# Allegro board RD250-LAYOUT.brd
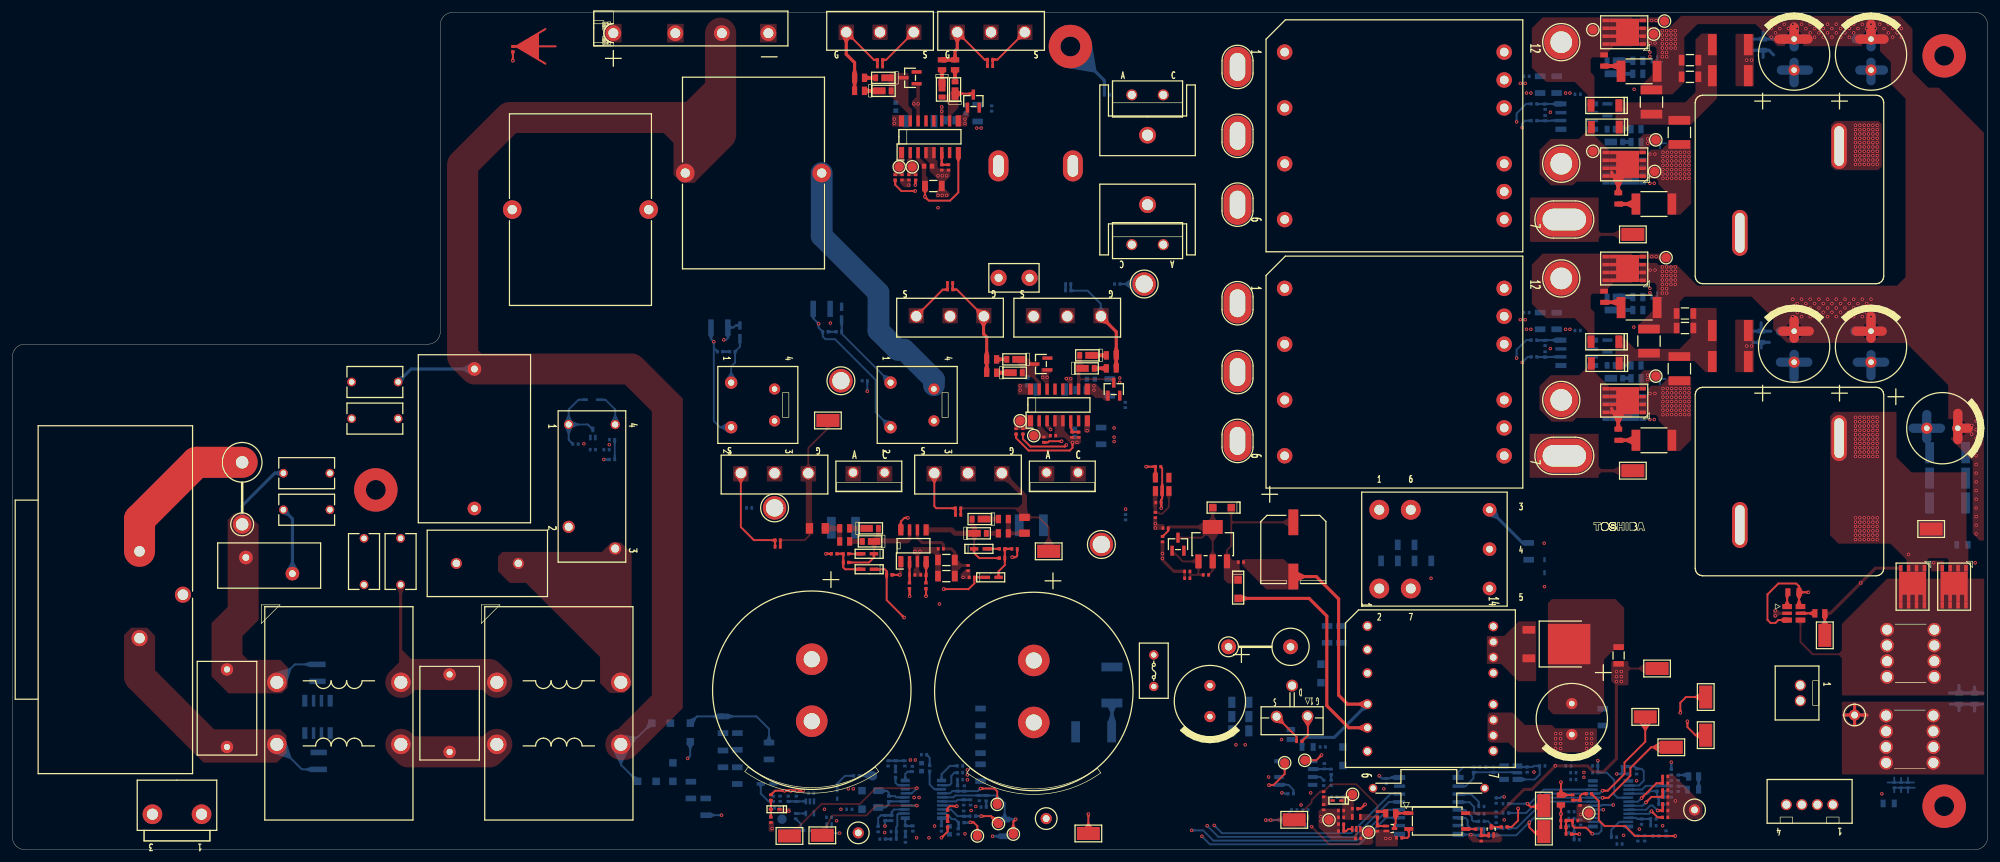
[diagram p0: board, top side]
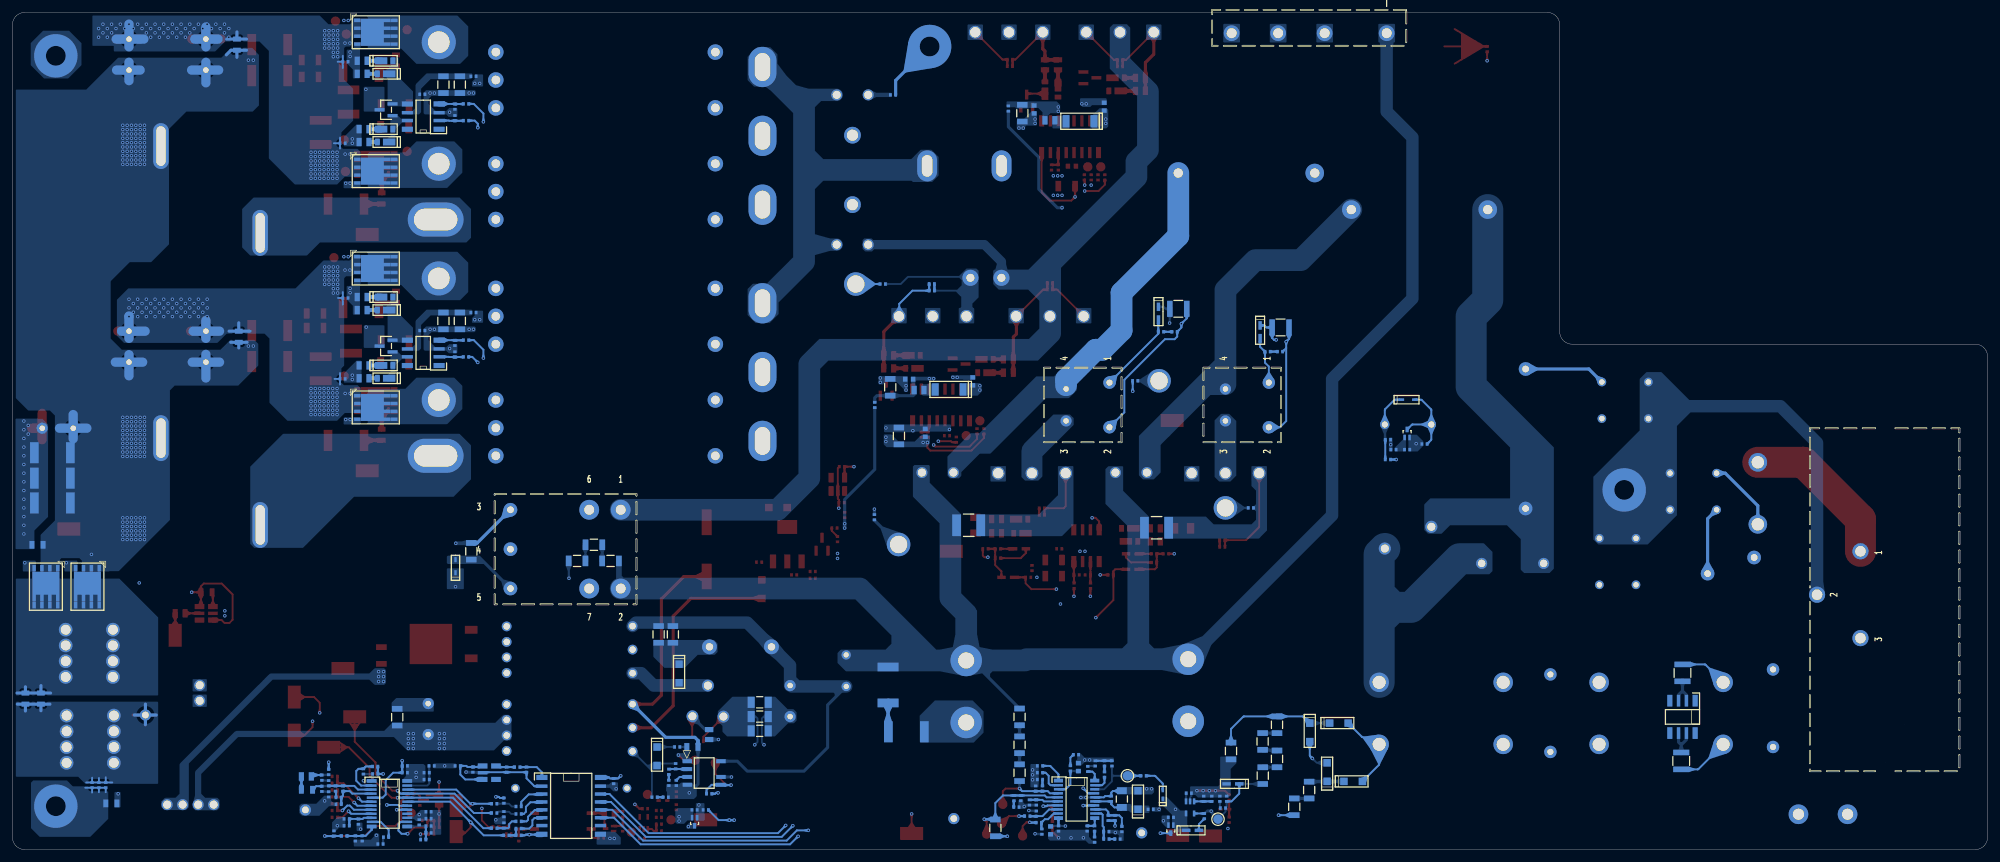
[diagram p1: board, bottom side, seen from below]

Outline 318.5 x 135 mm; copper layers: TOP, CONDUCTIVE2, CONDUCTIVE3, CONDUCTIVE4, CONDUCTIVE5, BOTTOM. Coordinates in mm from the lower left corner of the outline.
Outline path: 0,79.5 0.03,79.85 0.12,80.18 0.27,80.5 0.47,80.79 0.71,81.03 1,81.23 1.32,81.38 1.65,81.47 2,81.5 67,81.5 67.35,81.53 67.68,81.62 68,81.77 68.29,81.97 68.53,82.21 68.73,82.5 68.88,82.82 68.97,83.15 69,83.5 69,133 69.03,133.35 69.12,133.68 69.27,134 69.47,134.29 69.71,134.53 70,134.73 70.32,134.88 70.65,134.97 71,135 316.5,135 316.85,134.97 317.18,134.88 317.5,134.73 317.79,134.53 318.03,134.29 318.23,134 318.38,133.68 318.47,133.35 318.5,133 318.5,2 318.47,1.65 318.38,1.32 318.23,1 318.03,0.71 317.79,0.47 317.5,0.27 317.18,0.12 316.85,0.03 316.5,0 2,0 1.65,0.03 1.32,0.12 1,0.27 0.71,0.47 0.47,0.71 0.27,1 0.12,1.32 0.03,1.65 0,2 0,79.5

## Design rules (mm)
constraint set DEFAULT: 

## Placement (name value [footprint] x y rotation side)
C1  -  [FTP_73]  34.6 22.8 90 top
C2  -  [LOCAL_DE2E3SA222MN3AT02F]  51.2 60.7 180 top
C3  -  [LOCAL_DE2E3SA222MN3AT02F]  51.2 54.8 180 top
C4  -  [LOCAL_DE2E3SA222MN3AT02F]  62.6 50.2 270 top
C5  -  [LOCAL_DE2E3SA222MN3AT02F]  56.7 50.2 270 top
C6  -  [FTP_73]  70.5 22 90 top
C7  -  [LOCAL_DE2E3SA222MN3AT02F]  54.7 69.5 0 top
C8  -  [LOCAL_DE2E3SA222MN3AT02F]  54.7 75.4 0 top
C9  -  [FTP_75]  74.5 66.25 270 top
C11  -  [FTP_65#2]  96.7 62.9 180 bottom
C51  -  [LOCAL_AL_CAP_F30_A]  128.9 25.7 90 top
C52  -  [LOCAL_AL_CAP_F30_A]  164.7 25.5 90 top
C53  -  [FTP_65]  146.9 44.3 0 top
C54  -  [FTP_65]  145.1 44.3 180 top
C55  -  [FTP_15]  150.6 44.1 0 top
C56  -  [FTP_15]  150.6 46.7 0 top
C57  -  [FTP_65]  149.7 48.5 0 top
C58  -  [FTP_65#2]  114.1 80.3 180 bottom
C59  -  [FTP_65]  132.5 47.7 0 top
C60  -  [FTP_65#2]  131.1 83.5 180 bottom
C61  -  [FTP_65]  161.6 48.5 180 top
C62  -  [FTP_65#2]  152.5 2.9 270 bottom
C63  -  [FTP_65#2]  153.4 5.8 90 bottom
C64  -  [FTP_65#2]  155.9 8.3 270 bottom
C65  -  [FTP_65#2]  152.8 13.5 0 bottom
C66  -  [FTP_65#2]  141.2 13.9 90 bottom
C67  -  [FTP_24]  139.6 8.15 90 bottom
C68  -  [FTP_65#2]  141.3 8.2 90 bottom
C69  -  [FTP_67]  151.1 3.1 270 bottom
C70  -  [FTP_65#2]  139.6 3.3 270 bottom
C71  -  [FTP_65#2]  145.2 3.4 270 bottom
C72  -  [FTP_65#2]  144 3.4 270 bottom
C73  -  [FTP_65#2]  142.1 2.9 180 bottom
C74  -  [FTP_65#2]  142.1 1.7 180 bottom
C75  -  [FTP_67]  146.6 13.3 90 bottom
C76  -  [FTP_65#2]  147.9 13.1 90 bottom
C77  -  [FTP_65#2]  153.5 9.85 90 bottom
C78  -  [DC835R1AKP#2]  134 51.9 180 bottom
C79  -  [DC835R1AKP#2]  164.3 52.3 180 bottom
C81  -  [FTP_65]  152.5 55.05 0 top
C82  -  [FTP_65]  123.4 49.9 0 top
C101  -  [FTP_65]  144.55 108.4 90 top
C102  -  [FTP_65]  143.45 108.4 90 top
C103  -  [FTP_65]  150.95 110 90 top
C104  -  [FTP_15]  148.5 107 180 top
C105  -  [KC01670AKP]  147.65 110.2 180 top
C106  -  [FTP_15]  155.65 118.75 90 bottom
C107  -  [KC01670AKP#2]  153.75 119.35 270 bottom
C108  -  [KC01670AKP#2]  142.45 119.8 90 bottom
C109  -  [FTP_65]  139.9 127.35 180 top
C110  -  [FTP_65]  157.65 127.4 180 top
C111  -  [LOCAL_RDER73A104K5B1H03B_A]  164 92.2 180 top
C112  -  [FTP_65]  167.8 66.75 180 top
C113  -  [FTP_65]  161.85 67.45 90 top
C114  -  [FTP_65]  171.95 66.9 90 top
C115  -  [FTP_15]  175.55 66.7 90 bottom
C116  -  [KC01670AKP#2]  171.3 67.2 270 bottom
C117  -  [FTP_15]  176.95 74.55 270 bottom
C118  -  [KC01670AKP#2]  173.9 75.85 0 bottom
C119  -  [KC01670AKP#2]  163.65 75.5 90 bottom
C120  -  [FTP_65]  151.2 90.3 0 top
C121  -  [FTP_65#2]  170.25 90.12 180 bottom
C151  -  [FTP_15]  249 123.35 90 bottom
C152  -  [FTP_15]  246.35 123.35 90 bottom
C153  -  [FTP_65#2]  252.4 121.8 180 bottom
C154  -  [KC00060AKP]  258.95 105 90 top
C155  -  [KC00060AKP]  256.65 127.25 90 top
C156  -  [DC835R1AKP]  264.3 120.55 270 top
C157  -  [DC835R1AKP]  268.8 115.65 90 top
C158  -  [FTP_65#2]  247.15 117.95 90 bottom
C159  -  [FTP_65#2]  247.15 119.8 270 bottom
C201  -  [FTP_15]  246.35 85.25 90 bottom
C202  -  [FTP_15]  249 85.25 90 bottom
C203  -  [FTP_65#2]  252.4 83.7 180 bottom
C204  -  [KC00060AKP]  258.95 66.9 90 top
C205  -  [KC00060AKP]  256.65 89.15 90 top
C206  -  [DC835R1AKP]  263.9 82 270 top
C207  -  [DC835R1AKP]  268.8 77.55 90 top
C208  -  [FTP_65#2]  247.15 79.85 90 bottom
C209  -  [FTP_65#2]  247.15 81.7 270 bottom
C251  -  [FTP_65#2]  255.22 12.4 180 bottom
C252  -  [FTP_65#2]  251.7 12.4 0 bottom
C253  -  [FTP_65#2]  251.7 11.3 0 bottom
C254  -  [FTP_65#2]  260 12.2 180 bottom
C255  -  [FTP_65#2]  251.4 6.1 180 bottom
C256  -  [FTP_65#2]  265.9 8.4 0 bottom
C257  -  [FTP_65#2]  265.2 9.85 90 bottom
C258  -  [KC00060AKP#2]  271 9.65 180 bottom
C301  -  [FTP_15]  122 15.9 90 bottom
C302  -  [FTP_65#2]  122.7 8.2 90 bottom
C303  -  [FTP_65#2]  128.8 9.1 180 bottom
C304  -  [FTP_65#2]  126.4 8.2 90 bottom
C305  -  [FTP_65#2]  125.1 8.2 90 bottom
C306  -  [FTP_65]  217 1.8 0 top
C307  -  [FTP_65]  214.25 4.1 0 top
C308  -  [FTP_65]  214.25 3 0 top
C309  -  [FTP_65#2]  221.55 11.05 270 bottom
C310  -  [FTP_65]  214.25 5.2 0 top
C311  -  [FTP_65#2]  131.7 5.2 0 bottom
C351  -  [FTP_65#2]  235.6 12.9 270 bottom
C401  -  [FTP_13]  193.1 21.45 90 top
C402  -  [FTP_15]  212 34.7 90 bottom
C403  -  [FTP_15]  214.3 34.7 90 bottom
C405  -  [KC00060AKP#2]  208.85 16.55 180 bottom
C407  -  [FTP_65#2]  213.15 8.45 180 bottom
C408  -  [DC845R0AKP]  206.55 48.4 90 top
C409  -  [FTP_65]  198.1 46.35 180 top
C410  -  [FTP_65]  189.45 43.75 0 top
C411  -  [FTP_65]  185.45 50.05 90 top
C412  -  [FTP_65]  184.8 55.95 180 top
C413  -  [FTP_65]  184.75 61.75 180 top
C414  -  [SIK00180ATP_RD244_A]  224.65 9.9 0 top
C451  -  [FTP_13]  251.45 18.55 90 top
C452  -  [FTP_65#2]  244.25 12.9 270 bottom
C453  -  [FTP_65#2]  238.8 12.9 270 bottom
C501  -  [FTP_13]  287.3 130.7 270 top
C502  -  [FTP_13]  299.7 130.7 270 top
C503  -  [FTP_13]  313.7 67.95 180 top
C504  -  [FTP_13]  287.3 83.6 270 top
C505  -  [FTP_13]  299.7 83.6 270 top
C506  -  [KC00060AKP#2]  282 82.7 90 bottom
C507  -  [KC00060AKP#2]  282.3 129.8 90 bottom
C508  -  [KC00060AKP#2]  314.45 49.15 0 bottom
C509  -  [KC00060AKP]  287.2 41.5 0 top
C510  -  [KC00060AKP#2]  313.9 24.35 270 bottom
C511  -  [KC00060AKP#2]  316.4 24.35 270 bottom
C512  -  [KC00060AKP#2]  302.55 7.45 0 bottom
C513  -  [FTP_65#2]  303.45 10.4 90 bottom
CN1  -  [FTP_9]  4.7 40.3 270 top
CN2  -  [DJA415_ALG]  30.5 5.7 180 top
CN101  -  [LOCAL_LONGHOLE_250_450]  197.55 104 270 top
CN102  -  [LOCAL_LONGHOLE_250_450]  197.55 115.1 90 top
CN103  -  [LOCAL_LONGHOLE_250_450]  197.55 126.2 90 top
CN104  -  [LOCAL_LONGHOLE_250_450]  197.55 65.9 90 top
CN105  -  [LOCAL_LONGHOLE_250_450]  197.55 77 90 top
CN106  -  [LOCAL_LONGHOLE_250_450]  197.55 88.1 90 top
CN151  -  [LOCAL_TH350_P550]  249.75 110.6 0 top
CN152  -  [LOCAL_TH350_P550]  249.75 130.2 0 top
CN153  -  [LOCAL_LONGHOLE_350_700]  250.25 101.6 0 top
CN201  -  [LOCAL_TH350_P550]  249.75 72.5 0 top
CN202  -  [LOCAL_TH350_P550]  249.75 92.1 0 top
CN203  -  [LOCAL_LONGHOLE_350_700]  250.25 63.5 0 top
CN501  -  [LOCAL_7460305_A]  306.1 31.65 270 top
CN502  -  [LOCAL_7460305_A]  305.95 17.8 270 top
CN503  -  [CUK02330ATP]  288.3 26.5 270 top
CN504  -  [CUP10050ATP]  293.55 7.25 180 top
D1  -  [FTP_28]  93.45 72.55 0 bottom
D51  -  [MMK01670AKP]  109.3 18.9 90 bottom
D52  -  [MMK01670AKP]  104.6 20.4 0 bottom
D53  -  [MMK01670AKP]  106.5 12.5 270 bottom
D54  -  [MMK01670AKP]  102.3 11 0 bottom
D55  -  [LOCAL_GSIB2580_A]  96.9 131.65 0 top
D56  -  [LOCAL_TO_220_2L_A]  135.56 60.8 0 top
D57  -  [LOCAL_TO_220_2L_A]  166.76 60.8 0 top
D58  -  [FTP_20]  117.31 83.5 90 bottom
D59  -  [US2H_A]  138.4 51.8 0 top
D60  -  [US2H_A]  138.3 49.7 180 top
D61  -  [FTP_20]  137.9 47.7 0 top
D62  -  [FTP_20]  137.9 45.2 0 top
D63  -  [FTP_20]  133.7 86.5 90 bottom
D64  -  [US2H_A]  156 53.3 180 top
D65  -  [US2H_A]  155.8 51 0 top
D66  -  [FTP_20]  156.1 48.5 180 top
D67  -  [FTP_20]  158 43.9 180 top
D68  -  [FTP_85]  137 8 270 bottom
D101  -  [FTP_81]  146.35 117.45 180 bottom
D102  -  [US2H_A]  140.45 122.35 0 top
D103  -  [US2H_A]  140.45 124.45 180 top
D104  -  [FTP_27]  144.75 124.45 90 top
D105  -  [US2H_A]  149.9 122.6 270 top
D106  -  [US2H_A]  152 122.55 90 top
D107  -  [FTP_27]  154.95 120.7 0 top
D108  -  [DD504V]  185.58 97.55 180 top
D109  -  [DD504V]  180.5 121.7 0 top
D110  -  [FTP_81]  167.45 74.2 180 bottom
D111  -  [US2H_A]  161.6 76.9 0 top
D112  -  [US2H_A]  161.6 79.05 180 top
D113  -  [FTP_27]  165.85 78.3 90 top
D114  -  [US2H_A]  173.35 79.7 180 top
D115  -  [US2H_A]  173.2 77.6 0 top
D116  -  [FTP_27]  177.6 74.25 0 top
D151  -  [US2H_A]  258.4 116.17 180 bottom
D152  -  [US2H_A]  258.4 114.1 0 bottom
D153  -  [FTP_27]  258.25 119.3 90 bottom
D154  -  [US2H_A]  258.4 127.2 180 bottom
D156  -  [US2H_A]  258.4 125.1 0 bottom
D157  -  [FTP_81]  256.85 116.5 0 top
D158  -  [FTP_81]  256.8 120 0 top
D201  -  [US2H_A]  258.4 78.08 180 bottom
D202  -  [US2H_A]  258.4 76 0 bottom
D203  -  [FTP_27]  258.25 81.2 90 bottom
D204  -  [US2H_A]  258.4 89.1 180 bottom
D206  -  [US2H_A]  258.4 87 0 bottom
D207  -  [FTP_81]  256.85 78.4 0 top
D208  -  [FTP_81]  256.8 81.9 0 top
D251  -  [FTP_28]  247.05 45.7 270 bottom
D302  -  [D8K022]  121.7 10.6 180 bottom
D303  -  [FTP_20]  128.2 3.1 0 bottom
D304  -  [D8101D1AKP]  133 8.9 270 bottom
D305  -  [D8101D1AKP]  123 6.5 0 top
D306  -  [D8101D1AKP]  213.6 7.9 0 top
D401  -  [MMK01670AKP]  211 28.4 90 bottom
D402  -  [MMK01670AKP]  214.55 15.05 90 bottom
D403  -  [MMK01670AKP]  197.65 42 90 top
D404  -  [MMK01670AKP]  195.05 55.15 0 top
D405  -  [FTP_27]  187.95 49.25 0 top
D451  -  [DIC8V2]  249.6 33.15 270 top
DP1  -  [FTP_71]  166.7 5 0 top
DP51  -  [FTP_57]  173.5 2.6 0 top
DP52  -  [DTP815]  155.6 2.2 0 top
DP53  -  [FTP_57]  131.5 69.2 0 top
DP54  -  [DTP815]  159 4.2 0 top
DP55  -  [FTP_57]  167.1 48.1 0 top
DP56  -  [DTP815]  161.4 2.5 180 top
DP57  -  [FTP_57]  125.3 2.2 0 top
DP58  -  [FTP_57]  130.6 2.3 0 top
DP59  -  [FTP_71]  136.4 2.7 0 top
DP60  -  [DTP815]  158.8 7.3 0 top
DP61  -  [DTP815]  138.7 11.9 180 bottom
DP101  -  [DTP815]  143 110.1 0 top
DP102  -  [DTP815]  145.1 110.1 0 top
DP103  -  [DTP815]  162.5 69.15 0 top
DP104  -  [DTP815]  164.7 66.75 90 top
DP151  -  [DTP815]  254.85 112.6 0 top
DP152  -  [DTP815]  265 114.45 0 top
DP153  -  [DTP815]  264.8 109.35 0 top
DP154  -  [DTP815]  254.85 132.2 0 top
DP155  -  [DTP815]  266.4 133.6 0 top
DP156  -  [DTP815]  264.65 131.5 0 top
DP157  -  [FTP_57]  261.3 99.2 0 top
DP201  -  [DTP815]  265 76.35 0 top
DP202  -  [DTP815]  266.65 95.45 0 top
DP203  -  [FTP_57]  261.3 61.1 0 top
DP251  -  [FTP_57]  246.95 7.1 90 top
DP252  -  [FTP_57]  263.3 21.4 180 top
DP253  -  [FTP_57]  267.5 16.5 180 top
DP254  -  [FTP_57]  246.95 2.9 270 top
DP255  -  [FTP_57]  273.05 18.45 90 top
DP256  -  [FTP_57]  273.05 24.6 270 top
DP257  -  [FTP_71]  271.25 6.4 0 top
DP258  -  [DTP815]  254.2 5.9 0 top
DP301  -  [DTP815]  124.1 4.9 0 bottom
DP302  -  [DTP815]  216.1 8.9 0 top
DP303  -  [DTP815]  218.7 2.8 0 top
DP304  -  [DTP815]  212.3 4.8 0 top
DP401  -  [DTP815]  208.4 14.4 0 top
DP402  -  [DTP815]  205.15 14 90 top
DP403  -  [FTP_57]  206.7 4.8 180 top
DP404  -  [FTP_116]  122.9 55.1 0 top
DP405  -  [FTP_116]  175.6 49.2 0 top
DP406  -  [FTP_116]  133.6 75.6 0 top
DP407  -  [FTP_116]  182.5 91.2 0 top
DP451  -  [FTP_57]  265.2 29.2 0 top
DP501  -  [FTP_71]  297.05 21.7 0 top
DP502  -  [FTP_57]  292.25 34.55 90 top
DP503  -  [FTP_57]  309.4 51.7 0 top
F1  -  [LITTELFUSE_0215_PHI5_5_V_A_2]  37.05 62.45 270 top
F401  -  [F_I_808__0440_LF]  184.05 28.85 270 top
HS1  -  [LOCAL_BPUS15_25_A]  183.04 104 0 top
HS2  -  [LOCAL_BPUS15_25_A]  183.04 115.2 180 top
IC1  -  [FTP_60]  49.2 21.4 180 bottom
IC51  -  [FTP_112]  145.3 49 0 top
IC52  -  [FTP_128]  146.9 8.1 270 bottom
IC101  -  [I8K123]  147.95 114.95 0 top
IC102  -  [I8K123]  168.75 71.7 0 top
IC151  -  [FTP_112]  252.25 118.2 90 bottom
IC201  -  [FTP_112]  252.25 80.1 90 bottom
IC251  -  [FTP_61]  257.7 7.4 90 bottom
IC301  -  [MM00730AKP#2]  128.6 6.8 180 bottom
IC302  -  [MM00730AKP]  216.7 4.3 0 top
IC303  -  [LOCAL_4PIN_SO6L_A]  229.75 4.6 270 top
IC304  -  [LOCAL_I8K0A8]  228.4 7.05 90 bottom
IC401  -  [LOCAL_SOIC_7_A]  206.95 12.35 180 bottom
IC402  -  [MM01320AKP]  193.55 49.25 0 top
IC403  -  [DI8G1K]  185.4 58.9 0 top
IC451  -  [DI8G1K#2]  241.6 12.4 90 bottom
IC501  -  [SOT_23_6_KA]  287.25 38.1 270 top
L1  -  [LOCAL_LDFW013412YV_V0E_A]  52.64 21.97 0 top
L2  -  [LOCAL_LDFW013412YV_V0E_A]  88.11 21.97 0 top
L51  -  [FTP_118]  91.6 103.2 270 top
L52  -  [FTP_118]  119.5 109.1 270 top
L53  -  [FTP_55]  129.8 51.8 180 top
L54  -  [FTP_55]  163.2 52.3 90 top
L101  -  [LOCAL_TMSD_Y3001]  165 110.25 270 top
L151  -  [LOCAL_CTW18A27UH]  286.55 106.45 90 top
L201  -  [LOCAL_CTW18A27UH]  286.55 59.35 90 top
NOREF  -  []  168.8 71.7 0 top
NOREF#2  -  []  148 114.95 0 top
NOREF#3  -  [unnamed#2]  181.5 7 0 top
NOREF#4  -  []  170.6 129.5 0 top
NOREF#5  -  []  311.5 128 0 top
NOREF#6  -  []  58.6 58 0 top
NOREF#7  -  []  87.5 129.5 0 top
NOREF#8  -  [unnamed#2]  7 76.5 0 top
NOREF#9  -  []  311.5 7 0 top
NOREF#10  -  [unnamed#2]  73.5 128 0 top
NOREF#11  -  [unnamed#2]  180 128 0 top
NOREF#12  -  []  7 7 0 top
NOREF#13  -  []  253.8 50.3 0 top
Q1  -  [MM00340AKP]  93.6 67.1 180 bottom
Q51  -  [RDP10020ATP]  128.34 60.7 180 top
Q52  -  [RDP10020ATP]  159.54 60.7 180 top
Q101  -  [RDP10020ATP]  134.46 131.8 0 top
Q102  -  [RDP10020ATP]  152.36 131.8 0 top
Q103  -  [RDP10020ATP]  156.64 86 180 top
Q104  -  [RDP10020ATP]  175.54 86 180 top
Q151  -  [LOCAL_SOPADVANCE_E_01_A]  259.9 110.5 90 top
Q152  -  [LOCAL_SOPADVANCE_E_01_A]  259.9 109.4 270 bottom
Q153  -  [LOCAL_SOPADVANCE_E_01_A]  259.9 131.8 90 top
Q154  -  [LOCAL_SOPADVANCE_E_01_A]  259.9 131.8 270 bottom
Q201  -  [LOCAL_SOPADVANCE_E_01_A]  259.9 72.4 90 top
Q202  -  [LOCAL_SOPADVANCE_E_01_A]  259.9 71.3 270 bottom
Q203  -  [LOCAL_SOPADVANCE_E_01_A]  259.9 93.7 90 top
Q204  -  [LOCAL_SOPADVANCE_E_01_A]  259.9 93.7 270 bottom
Q301  -  [MM00340AKP]  222.2 3.4 270 top
Q302  -  [MM00340AKP]  131.7 3.3 0 bottom
Q303  -  [MM00340AKP]  208.5 4.5 0 bottom
Q351  -  [MM00340AKP]  238.45 3 0 top
Q401  -  [LOCAL_TO_220SIS_02_A]  206.35 21.45 180 top
Q501  -  [LOCAL_SOPADVANCE_E_01_A]  306.4 42.4 180 top
Q502  -  [LOCAL_SOPADVANCE_E_01_A]  313.1 42.4 180 top
Q503  -  [LOCAL_SOPADVANCE_E_01_A]  313.1 42.4 0 bottom
Q504  -  [LOCAL_SOPADVANCE_E_01_A]  306.4 42.4 0 bottom
R1  -  [FTP_49]  49.2 28.5 270 bottom
R2  -  [FTP_49]  49.4 14.3 270 bottom
R3  -  [LOCAL_Y5JA_330JPTL3_5_A]  76.58 46.15 180 top
R4  -  [KC00050AKP#2]  96.7 66.1 0 bottom
R5  -  [KC00050AKP#2]  93.6 64.5 180 bottom
R6  -  [KC00050AKP#2]  90.8 65.4 0 bottom
R7  -  [KC00050AKP#2]  95.8 64.5 0 bottom
R51  -  [KC00050AKP]  154.1 45.4 90 top
R52  -  [FTP_49]  114.01 84.2 180 bottom
R53  -  [KC00050AKP#2]  116.1 80.3 180 bottom
R54  -  [DR810K]  134.2 49.7 180 top
R55  -  [DR810K]  134.2 51.8 180 top
R56  -  [KC00050AKP]  123.4 48.8 0 top
R57  -  [KC00050AKP]  134.4 46.3 180 top
R58  -  [KC00050AKP]  134.4 47.7 180 top
R59  -  [KC00050AKP]  141.4 44.3 0 top
R60  -  [FTP_49]  130.5 87.2 180 bottom
R61  -  [KC00050AKP#2]  133.3 83.5 180 bottom
R62  -  [DR810K]  159.8 51 0 top
R63  -  [DR810K]  159.8 53.3 0 top
R64  -  [KC00050AKP]  152.5 53.95 0 top
R65  -  [KC00050AKP]  159.6 47 0 top
R66  -  [KC00050AKP]  159.6 48.5 0 top
R67  -  [KC00050AKP]  154.7 43.9 180 top
R68  -  [KC00050AKP#2]  153 4.35 0 bottom
R69  -  [KC00050AKP#2]  154.85 5.4 0 bottom
R70  -  [FTP_50#2]  109.4 9.6 270 bottom
R71  -  [FTP_50#2]  111.8 6.9 270 bottom
R72  -  [FTP_50#2]  160 3.5 90 bottom
R73  -  [KC00050AKP#2]  157 8.3 270 bottom
R74  -  [KC00050AKP#2]  156.6 6.85 180 bottom
R76  -  [KC00050AKP#2]  152.8 12.4 0 bottom
R77  -  [KC00050AKP#2]  145.1 13 90 bottom
R78  -  [KC00050AKP#2]  143.9 13.9 90 bottom
R79  -  [KC00050AKP#2]  153.4 7.6 270 bottom
R80  -  [KC00050AKP#2]  154.5 7.6 270 bottom
R81  -  [KC00050AKP]  150.8 5.9 90 top
R82  -  [KC00050AKP]  150.8 4.1 90 top
R83  -  [KC00050AKP#2]  142.4 12.1 90 bottom
R84  -  [KC00050AKP#2]  142.4 13.9 90 bottom
R85  -  [KC00050AKP#2]  134.95 6.5 180 bottom
R86  -  [KC00050AKP#2]  140.7 5.1 270 bottom
R87  -  [KC00050AKP#2]  141.8 5.1 270 bottom
R88  -  [KC00050AKP#2]  149.8 3.4 270 bottom
R89  -  [KC00050AKP#2]  144 1.6 270 bottom
R90  -  [KC00050AKP#2]  140.3 1.7 180 bottom
R91  -  [KC00050AKP#2]  147 15.3 180 bottom
R92  -  [FTP_50#2]  156.1 21.4 270 bottom
R93  -  [FTP_50#2]  156.1 16.9 270 bottom
R94  -  [FTP_50#2]  156.1 12.4 270 bottom
R95  -  [KC00050AKP#2]  152.4 9.85 90 bottom
R96  -  [KC00050AKP#2]  152.8 11.3 0 bottom
R97  -  [KC00050AKP]  144.65 42.55 90 top
R98  -  [KC00050AKP]  147.3 42.55 90 top
R101  -  [R8100A#2]  177.3 26.55 270 bottom
R102  -  [R8100A#2]  174.35 19 180 bottom
R103  -  [KC00050AKP]  145.65 108.4 270 top
R104  -  [KC00050AKP]  142.35 108.4 270 top
R105  -  [KC00050AKP]  149.85 110 270 top
R106  -  [KC00050AKP#2]  157.9 119.5 270 bottom
R107  -  [DR810K#2]  151.2 117.6 180 bottom
R108  -  [DR810K]  136.6 122.35 180 top
R109  -  [DR810K]  136.6 124.45 180 top
R110  -  [KC00050AKP]  139.9 126.25 180 top
R111  -  [DR810K]  149.9 126.55 90 top
R112  -  [DR810K]  152 126.55 90 top
R113  -  [KC00050AKP]  157.65 126.3 180 top
R114  -  [KC00050AKP]  166.3 66.1 270 top
R115  -  [KC00050AKP]  162.95 67.45 270 top
R116  -  [KC00050AKP]  170.85 66.9 270 top
R117  -  [KC00050AKP#2]  179.45 71.7 270 bottom
R118  -  [DR810K#2]  172.3 74.1 180 bottom
R119  -  [DR810K]  157.9 76.9 180 top
R120  -  [DR810K]  157.9 79.05 180 top
R121  -  [KC00050AKP]  151.2 91.4 0 top
R122  -  [DR810K]  177.2 79.7 0 top
R123  -  [DR810K]  177.2 77.6 0 top
R124  -  [KC00050AKP#2]  170.25 91.22 180 bottom
R151  -  [KC00050AKP#2]  244.15 124.7 180 bottom
R152  -  [DR810K#2]  261.8 116.17 180 bottom
R153  -  [DR810K#2]  261.8 114.1 180 bottom
R154  -  [KC00050AKP#2]  265.25 113.9 0 bottom
R155  -  [FTP_106]  264.7 104.1 180 top
R156  -  [DR810K#2]  262.1 127.2 180 bottom
R157  -  [DR810K#2]  262.1 125.1 180 bottom
R158  -  [KC00050AKP#2]  264.8 127.05 0 bottom
R159  -  [FTP_106]  262.3 125.5 180 top
R160  -  [FTP_50]  270.5 127.31 0 top
R161  -  [FTP_50]  270.5 124.61 0 top
R162  -  [R8100A]  277 129.8 0 top
R163  -  [R8100A]  277 124.8 0 top
R164  -  [KC00050AKP#2]  245.35 117.55 180 bottom
R165  -  [KC00050AKP#2]  245.35 120.25 180 bottom
R201  -  [KC00050AKP#2]  244.15 86.6 180 bottom
R202  -  [DR810K#2]  261.8 78.08 180 bottom
R203  -  [DR810K#2]  261.8 76 180 bottom
R204  -  [KC00050AKP#2]  265.25 75.9 0 bottom
R205  -  [FTP_106]  264.7 66 180 top
R206  -  [DR810K#2]  262.1 89.1 180 bottom
R207  -  [DR810K#2]  262.1 87 180 bottom
R208  -  [KC00050AKP#2]  264.8 88.95 0 bottom
R209  -  [FTP_106]  262.3 87.4 180 top
R210  -  [FTP_50]  269.7 86.45 0 top
R211  -  [FTP_50]  269.7 84.11 0 top
R212  -  [R8100A]  277 83.7 0 top
R213  -  [R8100A]  277 78.7 0 top
R214  -  [KC00050AKP#2]  245.35 79.45 180 bottom
R215  -  [KC00050AKP#2]  245.35 82.15 180 bottom
R251  -  [FTP_50#2]  244.5 48.1 90 bottom
R252  -  [KC00050AKP#2]  255.22 13.5 180 bottom
R253  -  [KC00050AKP]  266.52 11.8 180 top
R254  -  [KC00050AKP]  266.52 10.7 180 top
R255  -  [KC00050AKP]  266.52 9.6 180 top
R256  -  [KC00050AKP]  266.52 8.5 180 top
R257  -  [KC00050AKP]  266.52 7.4 180 top
R258  -  [KC00050AKP]  266.52 6.3 180 top
R259  -  [KC00050AKP]  266.52 5.2 180 top
R260  -  [KC00050AKP#2]  250.9 13.5 180 bottom
R261  -  [KC00050AKP#2]  258.25 2 0 bottom
R262  -  [KC00050AKP#2]  259.15 0.9 0 bottom
R263  -  [KC00050AKP#2]  264.6 3.85 180 bottom
R264  -  [KC00050AKP#2]  262.7 4.5 270 bottom
R265  -  [KC00050AKP#2]  264.6 4.95 180 bottom
R266  -  [KC00050AKP#2]  252.9 4.4 270 bottom
R267  -  [KC00050AKP#2]  251.4 3.8 180 bottom
R268  -  [KC00050AKP#2]  252.25 1.6 180 bottom
R269  -  [KC00050AKP#2]  251.4 2.7 180 bottom
R270  -  [KC00050AKP]  250.95 2.5 0 top
R271  -  [KC00050AKP]  250.1 4.7 0 top
R272  -  [KC00050AKP#2]  261.9 12.6 90 bottom
R273  -  [KC00050AKP#2]  260 13.4 180 bottom
R274  -  [KC00050AKP]  252 4.7 0 top
R275  -  [KC00050AKP]  250.1 3.6 0 top
R276  -  [KC00050AKP#2]  251.4 5 180 bottom
R277  -  [KC00050AKP]  252.8 7.55 90 top
R278  -  [KC00050AKP]  254.2 9 180 top
R279  -  [KC00050AKP#2]  266.65 2.6 270 bottom
R280  -  [KC00050AKP#2]  265 2.2 180 bottom
R281  -  [KC00050AKP#2]  262.1 1.8 270 bottom
R282  -  [KC00050AKP]  251.6 8.4 90 top
R283  -  [KC00050AKP#2]  263.2 1.8 270 bottom
R284  -  [DR810K]  249.7 8 90 top
R285  -  [KC00050AKP#2]  265.9 7.3 0 bottom
R286  -  [KC00050AKP#2]  266.4 9.85 270 bottom
R287  -  [KC00050AKP#2]  267.5 12.5 270 bottom
R288  -  [KC00050AKP#2]  268.6 11.6 270 bottom
R289  -  [KC00050AKP#2]  267.5 10.7 270 bottom
R290  -  [KC00050AKP#2]  268.6 9.8 270 bottom
R291  -  [KC00050AKP#2]  267.5 8.9 270 bottom
R292  -  [DR810K#2]  271.1 11.8 0 bottom
R301  -  [FTP_50#2]  114.58 20.13 90 bottom
R302  -  [FTP_50#2]  116.9 17.44 90 bottom
R303  -  [FTP_50#2]  114.58 14.63 90 bottom
R304  -  [FTP_50#2]  116.88 11.93 90 bottom
R305  -  [KC00050AKP#2]  123.3 6.7 0 bottom
R306  -  [KC00050AKP#2]  123.8 8.2 90 bottom
R307  -  [KC00050AKP#2]  126.3 5.4 90 bottom
R308  -  [KC00050AKP#2]  136.1 11.9 0 bottom
R309  -  [FTP_50#2]  222.05 46.55 180 bottom
R310  -  [FTP_50#2]  224.74 49.15 180 bottom
R311  -  [FTP_50#2]  227.45 46.55 180 bottom
R312  -  [KC00050AKP]  214.25 6.3 0 top
R313  -  [KC00050AKP]  216.5 6.6 0 top
R314  -  [KC00050AKP]  220.1 5.7 90 top
R315  -  [KC00050AKP]  220.1 3.4 90 top
R316  -  [DR810K]  222.25 5.85 180 top
R317  -  [KC00050AKP]  223.6 1.9 0 top
R318  -  [KC00050AKP#2]  206.7 6.4 0 bottom
R319  -  [KC00050AKP#2]  208.5 6.4 0 bottom
R320  -  [KC00050AKP]  122.3 4.8 270 top
R321  -  [KC00050AKP]  122.3 8.4 270 top
R322  -  [KC00050AKP]  211.44 8.92 90 top
R323  -  [KC00050AKP]  211.44 6.82 90 top
R351  -  [KC00050AKP]  236.45 3.3 180 top
R352  -  [KC00050AKP]  236.85 1.8 90 top
R353  -  [KC00050AKP]  240.55 3.65 0 top
R354  -  [KC00050AKP#2]  236.88 6.95 0 bottom
R355  -  [KC00050AKP#2]  240.8 7.4 180 bottom
R356  -  [KC00050AKP#2]  239.25 7.9 90 bottom
R357  -  [KC00050AKP#2]  236.88 5.75 0 bottom
R358  -  [KC00050AKP#2]  240.8 5.9 180 bottom
R359  -  [KC00050AKP#2]  239.25 5.7 270 bottom
R360  -  [KC00050AKP#2]  236.88 4.55 0 bottom
R361  -  [KC00050AKP#2]  240.8 3.45 180 bottom
R362  -  [KC00050AKP#2]  239.25 3.9 90 bottom
R363  -  [KC00050AKP#2]  236.88 3.4 0 bottom
R364  -  [KC00050AKP#2]  238.85 2.3 180 bottom
R365  -  [KC00050AKP#2]  236.88 2.3 180 bottom
R401  -  [FTP_98]  206.1 32.7 180 top
R402  -  [DR810K#2]  206.15 18.55 270 bottom
R403  -  [KC00050AKP]  207.5 17.45 0 top
R404  -  [KC00140AKP01]  198 23.75 180 bottom
R405  -  [KC00140AKP01]  198 21.45 180 bottom
R406  -  [KC00140AKP01]  198 19.15 180 bottom
R407  -  [KC00050AKP#2]  206.15 9 0 bottom
R408  -  [KC00050AKP#2]  211.3 16.55 180 bottom
R409  -  [KC00050AKP#2]  211.55 13.45 270 bottom
R410  -  [KC00050AKP#2]  212.65 12.55 270 bottom
R411  -  [KC00050AKP#2]  212.65 10.75 270 bottom
R412  -  [KC00050AKP#2]  211.45 10.75 270 bottom
R413  -  [KC00050AKP#2]  214.95 8.45 180 bottom
R414  -  [KC00050AKP]  189.45 44.85 0 top
R415  -  [KC00050AKP]  192.45 44.3 0 top
R416  -  [KC00050AKP]  185.95 51.85 0 top
R417  -  [KC00050AKP]  184.3 53.95 90 top
R418  -  [KC00050AKP#2]  118.8 55.1 180 bottom
R419  -  [KC00050AKP#2]  179.5 53.6 90 bottom
R420  -  [KC00050AKP#2]  137.45 75.6 0 bottom
R421  -  [KC00050AKP#2]  178.15 91.2 180 bottom
R422  -  [KC00050AKP]  80.7 129.1 90 top
R423  -  [KC00050AKP#2]  176.5 121.7 0 bottom
R451  -  [FTP_50#2]  256.45 21.35 270 bottom
R452  -  [FTP_50]  259 31.3 270 top
R453  -  [KC00050AKP#2]  246.7 13.5 0 bottom
R454  -  [KC00050AKP#2]  237.1 13.3 0 bottom
R501  -  [R8100A#2]  312.05 64 0 bottom
R502  -  [R8100A#2]  312.05 59.9 0 bottom
R503  -  [R8100A#2]  312.05 55.9 0 bottom
R504  -  [DR810K]  291.45 38.1 0 top
R505  -  [KC00050AKP#2]  304.55 10.39 270 bottom
R506  -  [KC00050AKP#2]  305.65 10.4 270 bottom
RV1  -  [FTP_120]  41.4 45.8 0 top
RY1  -  [LOCAL_G5PZ_1A]  89.7 68.55 270 top
T51  -  [FTP_94]  120.2 71.7 270 top
T52  -  [FTP_94]  145.9 71.7 270 top
T101  -  [FTP_96]  229.3 48.45 0 top
T151  -  [LOCAL_TAM0545]  222.85 115.1 270 top
T201  -  [LOCAL_TAM0545]  222.85 77 270 top
T401  -  [LOCAL_TAM_PQ20_36_5]  228.65 25.95 270 top

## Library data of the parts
C1 C6 = PRT_17: alternate symbols: (T:FTP_73;B:FTP_74)
C2 C3 = DE2B3SA101KA3BT02F
C4 C5 C7 C8 = DE2E3SA222MN3AT02F: alternate symbols: (T:Local_DE2E3SA222MN3AT02F;B:Local_DE2E3SA222MN3AT02F_B)
C9 = PRT_18: alternate symbols: (T:FTP_75;B:FTP_76)
C11 C53 C54 C57-C66 C68 C70-C74 C76 C77 C81 C82 C101-C103 C109 C110 C112-C114 C120 C121 C153 C158 C159 C203 C208 C209 C251-C257 C302-C311 C351 C407 C409-C413 C452 C453 C513 = PRT_52: alternate symbols: (T:FTP_65;B:FTP_66)
C51 C52 = EKHE421VSN561MR35Z: alternate symbols: (T:Local_AL_CAP_f30_A;B:Local_AL_CAP_f30_A_B)
C55 C56 C104 C106 C115 C117 C151 C152 C201 C202 C301 C402 C403 = PRT_46: alternate symbols: (T:FTP_15;B:FTP_16)
C67 = PRT_51: alternate symbols: (T:FTP_24;B:FTP_25)
C69 C75 = PRT_48: alternate symbols: (T:FTP_67;B:FTP_68)
C78 C79 = C4532: alternate symbols: (T:DC835R1AKP;B:DC835R1BKP)
C105 C107 C108 C116 C118 C119 = C1608: alternate symbols: (T:KC01670AKP;B:KC01670BKP)
C111 = RDER73A104K5B1H03B: alternate symbols: (T:Local_RDER73A104K5B1H03B_A;B:Local_RDER73A104K5B1H03B_A_B)
C154 C155 C204 C205 C405 C506-C512 = GRM21BC71E106KE01: alternate symbols: (T:KC00060AKP;B:KC00060BKP)
C156 C157 C206 C207 = K0301583: alternate symbols: (T:DC835R1AKP;B:DC835R1BKP)
C258 = C2012: alternate symbols: (T:KC00060AKP;B:KC00060BKP)
C401 C451 C501-C505 = PRT_3: alternate symbols: (T:FTP_13;B:FTP_14)
C408 = EMLA350ARA331MJA0G: alternate symbols: (T:DC845R0AKP;B:DC845R0BKP)
C414 = DE2B3SA221KA3BT02F: alternate symbols: (T:SIK00180ATP_RD244_A;B:SIK00180ATP_RD244_A_B)
CN1 = PRT_61: alternate symbols: (T:FTP_9;B:FTP_10)
CN2 = G36220401068: alternate symbols: (T:DJA415_ALG;B:DA415R_ALG)
CN101-CN106 = Longhole_2R5-4R5: alternate symbols: (T:Local_LONGHOLE_250_450;B:Local_LONGHOLE_250_450_B)
CN151 CN152 CN201 CN202 = TH_phi_3R5: alternate symbols: (T:Local_TH350_P550;B:Local_TH350_P550_B)
CN153 CN203 = Longhole_3R5-7R0: alternate symbols: (T:Local_LONGHOLE_350_700;B:Local_LONGHOLE_350_700_B)
CN501 CN502 = 7460305: alternate symbols: (T:Local_7460305_A;B:Local_7460305_A_B)
CN503 = K2203993: alternate symbols: (T:CUK02330ATP;B:CUK02330BTP)
CN504 = K22S0019: alternate symbols: (T:CUP10050ATP;B:CUP10050BTP)
D1 D251 = PRT_26: alternate symbols: (T:FTP_28;B:FTP_32)
D51-D54 = CRG04A: alternate symbols: (T:MMK01670AKP;B:MMK01670BKP)
D55 = GSIB2580: alternate symbols: (T:Local_GSIB2580_A;B:NO_D0001A)
D56 D57 = SBD_TO-220-2L: alternate symbols: (T:Local_TO_220_2L_A;B:Local_TO_220_2L_A_B)
D58 D61-D63 D66 D67 D303 = PRT_27: alternate symbols: (T:FTP_20;B:FTP_22)
D59 D60 D64 D65 D102 D103 D105 D106 D111 D112 D114 D115 D151 D152 D154 D156 D201 D202 D204 D206 = CUHS15S30: alternate symbols: (T:US2H_A;B:US2H_B)
D68 = PRT_6: alternate symbols: (T:FTP_85;B:FTP_86)
D101 D110 D157 D158 D207 D208 = PRT_14: alternate symbols: (T:FTP_81;B:FTP_82)
D104 D107 D113 D116 D153 D203 D405 = PRT_25: alternate symbols: (T:FTP_27;B:FTP_31)
D108 D109 = TRS8E65H: alternate symbols: (T:DD504V;B:DD504V_B)
D302 = ZenerDiode_USC-01: alternate symbols: (T:D8K022;B:D9K022)
D304-D306 = 1SS405: alternate symbols: (T:D8101D1AKP;B:D8101D1BKP)
D401 = CRF03A: alternate symbols: (T:MMK01670AKP;B:MMK01670BKP)
D402 D403 = GDM420000387: alternate symbols: (T:MMK01670AKP;B:MMK01670BKP)
D404 = K4200730: alternate symbols: (T:MMK01670AKP;B:MMK01670BKP)
D451 = NJM78M05SDL1-TE1: alternate symbols: (T:DIC8V2;B:DIC9V2)
DP1 DP59 = PRT_49: alternate symbols: (T:FTP_71;B:FTP_72)
DP51 DP53 DP55 DP57 DP58 DP157 DP203 DP251-DP256 DP403 DP451 DP502 DP503 = PRT_44: alternate symbols: (T:FTP_57;B:FTP_58)
DP52 DP54 DP56 DP60 DP61 DP101-DP104 DP151-DP156 DP201 DP202 DP258 DP301-DP304 DP401 DP402 = DTP815: alternate symbols: (T:DTP815;B:DTP915)
DP257 DP501 = PRT_34: alternate symbols: (T:FTP_71;B:FTP_72)
DP404-DP407 = PRT_39: alternate symbols: (T:FTP_116;B:FTP_117)
F1 = 0215015.MXEP: alternate symbols: (T:Littelfuse_0215_phi5_5_V_A_2;B:Littelfuse_0215_phi5_5_V_B_2)
F401 = 808****0440_LF: alternate symbols: (T:F_I_808__0440_LF;B:F_I_808__0440_LF_B)
HS1 HS2 = BPUS15-25: alternate symbols: (T:Local_BPUS15_25_A;B:Local_BPUS15_25_B)
IC1 = PRT_45: alternate symbols: (T:FTP_60;B:FTP_63)
IC51 IC151 IC201 = PRT_63: alternate symbols: (T:FTP_112;B:FTP_113)
IC52 = PRT_59: alternate symbols: (T:FTP_128;B:FTP_129)
IC101 IC102 = UCC21330: alternate symbols: (T:I8K123;B:I9K123)
IC251 = PRT_16: alternate symbols: (T:FTP_61;B:FTP_64)
IC301 IC302 = GDM470001845: alternate symbols: (T:MM00730AKP;B:MM00730BKP)
IC303 = TLP385: alternate symbols: (T:Local_4pin_SO6L_A;B:Local_4pin_SO6L_B)
IC304 = DCL540C01: alternate symbols: (T:Local_I8K0A8;B:LocalI9K0A8)
IC401 = UCC28711DR: alternate symbols: (T:Local_SOIC_7_A;B:Local_SOIC_7_B)
IC402 = LM317MDCY: alternate symbols: (T:MM01320AKP;B:MM01320BKP)
IC403 IC451 = TCR1HF50B: alternate symbols: (T:DI8G1K;B:DI9G1K)
IC501 = LM74700-Q1: alternate symbols: (T:SOT_23_6_KA;B:SOT_23_6_KB)
L1 L2 = LDFW013412YV-V0E: alternate symbols: (T:Local_LDFW013412YV_V0E_A;B:Local_LDFW013412YV_V0E_B)
L51 L52 = PRT_41: alternate symbols: (T:FTP_118;B:FTP_119)
L53 L54 = PRT_30: alternate symbols: (T:FTP_55;B:FTP_56)
L101 = TMSD-Y3001: alternate symbols: (T:Local_TMSD_Y3001;B:Local_TMSD_Y3001_B)
L151 L201 = CTW18A27uH: alternate symbols: (T:Local_CTW18A27uH;B:Local_CTW18A27uH_B)
Q1 Q301-Q303 Q351 = GDM410000663: alternate symbols: (T:MM00340AKP;B:MM00340BKP)
Q51 Q52 = TK125N60Z1: alternate symbols: (T:RDP10020ATP;B:RDP10020BTP)
Q101-Q104 = TK095N65Z5: alternate symbols: (T:RDP10020ATP;B:RDP10020BTP)
Q151-Q154 Q201-Q204 Q501-Q504 = NchMOSFET_SOPAdvance(E)-01: alternate symbols: (T:Local_SOPAdvance_E_01_A;B:Local_SOPAdvance_E_01_B)
Q401 = K4100860: alternate symbols: (T:Local_TO_220SIS_02_A;B:NO_Q00001)
R1 R2 R52 R60 = PRT_23: alternate symbols: (T:FTP_49;B:FTP_52)
R3 = Y5JA-330JPTL3_5: alternate symbols: (T:Local_Y5JA_330JPTL3_5_A;B:Local_Y5JA_330JPTL3_5_A_B)
R4-R7 R51 R53 R56-R59 R61 R64-R69 R73 R74 R76-R91 R95-R98 R103-R106 R110 R113-R117 R121 R124 R151 R154 R158 R164 R165 R201 R204 R208 R214 R215 R252-R283 R285-R291 R305-R308 R312-R315 R317-R323 R351-R365 R403 R407-R423 R453 R454 R505 R506 = GDM010004481: alternate symbols: (T:KC00050AKP;B:KC00050BKP)
R54 R55 R62 R63 R107-R109 R111 R112 R118-R120 R122 R123 R152 R153 R156 R157 R202 R203 R206 R207 R284 R292 R316 R402 R504 = R2012: alternate symbols: (T:DR810K;B:DR910K)
R70-R72 R92-R94 R160 R161 R210 R211 R251 R301-R304 R309-R311 R451 R452 = PRT_5: alternate symbols: (T:FTP_50;B:FTP_51)
R101 R102 R501-R503 = GDM010001640: alternate symbols: (T:R8100A;B:R9100A)
R155 R159 R205 R209 = PRT_43: alternate symbols: (T:FTP_106;B:FTP_107)
R162 R163 R212 R213 = CRGH2512J620R: alternate symbols: (T:R8100A;B:R9100A)
R401 = PRT_54: alternate symbols: (T:FTP_98;B:FTP_99)
R404-R406 = R3216: alternate symbols: (T:KC00140AKP01;B:KC00140BKP01)
RV1 = PRT_37: alternate symbols: (T:FTP_120;B:FTP_121)
RY1 = G5PZ-1A: alternate symbols: (T:Local_G5PZ_1A;B:Local_G5PZ_1A_B)
T51 T52 = PRT_7: alternate symbols: (T:FTP_94,T52_FTP_94;B:FTP_95)
T101 = PRT_65: alternate symbols: (T:FTP_96;B:FTP_97)
T151 T201 = TAM0545: alternate symbols: (T:Local_TAM0545;B:Local_TAM0545_B)
T401 = WT2020B: alternate symbols: (T:Local_TAM_PQ20_36_5;B:Local_TAM_PQ20_36_5_B)

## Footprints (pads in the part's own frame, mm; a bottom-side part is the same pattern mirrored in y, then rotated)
CUK02330ATP
  round 1.778 hole 1.3: 1(0,0) 2(2.5,0)
CUP10050ATP
  round 1.778 hole 1.3: 1(0,0) 2(2.5,0) 3(5,0) 4(7.5,0)
D8K022
  rect 1.36x0.55 smd: A(-1.025,0) C(1.025,0)
D8101D1AKP
  rect 0.7x0.4 smd: A(-0.7,0) C(0.7,0)
DC835R1AKP
  rect 1.41x3.5 smd: 1(-1.95,0) 2(1.95,0)
DC835R1AKP#2
  rect 1.41x3.5 smd: 1(1.95,0) 2(-1.95,0)
DC845R0AKP
  rect 4.15x1.6 smd: 1(-4.375,0) 2(4.375,0)
DD504V
  round 1.778 hole 1.3: A(0,0) C(5.08,0)
DI8G1K
  rect 0.825x1.56 smd: 1(-1.087,-1.075) 3(1.087,-1.075) 4(1.087,1.075) 5(-1.087,1.075)
  rect 0.55x1.56 smd: 2(0,-1.075)
DI8G1K#2
  rect 0.825x1.56 smd: 1(1.087,1.075) 3(-1.087,1.075) 4(-1.087,-1.075) 5(1.087,-1.075)
  rect 0.55x1.56 smd: 2(0,1.075)
DIC8V2
  rect 1.25x2.049 smd: 1(-2.3,-5.075) 3(2.3,-5.075)
  rect 6.5x6.85 smd: 2(0,1.425)
DJA415_ALG
  round 3.175 hole 1.8: 1(0,0) 3(7.92,0)
  round 0 hole 1.8: 2(3.96,0)
DR810K
  rect 0.83x1.35 smd: 1(-0.8,0) 2(0.8,0)
DR810K#2
  rect 0.83x1.35 smd: 1(0.8,0) 2(-0.8,0)
DTP815
  round 1.5 smd: 1(0,0)
F_I_808__0440_LF
  round 1.5 hole 0.85: 1(-2.54,0) 2(2.54,0)
FTP_9
  round 0.01 hole 2.6x4 unplated: (-26.2,11.8) (26.2,11.8)
  round 0.01 hole 3.6 unplated: (-20.05,8.75) (20.05,8.75)
  round 2.6 hole 1.7: 1(-7.8,15.8) 2(-0.8,22.8) 3(6.2,15.8)
FTP_13
  round 1.8 hole 0.9: 1(0,0) 2(5,0)
FTP_15
  rect 0.92x1.7 smd: 1(-1.35,0) 2(1.35,0)
FTP_20
  rect 1.36x0.55 smd: A(-1.025,0) C(1.025,0)
FTP_24
  rect 1.1x1.6 smd: 1(1.35,0) 2(-1.35,0)
FTP_27
  rect 0.55x1.61 smd: A(-0.95,-1.05) C(0,1.05) NC(0.95,-1.05)
FTP_28
  rect 0.824x0.4 smd: A(-1.05,0) C(1.05,0)
FTP_49
  rect 0.895x2.6 smd: 1(1.363,0) 2(-1.363,0)
FTP_50
  rect 0.92x1.7 smd: 1(-1.35,0) 2(1.35,0)
FTP_50#2
  rect 0.92x1.7 smd: 1(1.35,0) 2(-1.35,0)
FTP_55
  rect 1.17x1.7 smd: 1(-1.275,0) 2(1.275,0)
FTP_57
  rect 3.7x2.1 smd: 1(0,0)
FTP_60
  rect 0.825x1.885 smd: 1(2.042,2.612) 4(-2.042,2.612) 5(-2.042,-2.612) 8(2.042,-2.612)
  rect 0.55x1.885 smd: 2(0.635,2.612) 3(-0.635,2.612) 6(-0.635,-2.612) 7(0.635,-2.612)
FTP_61
  rect 0.6x1.585 smd: 1(3.675,2.862) 12(-3.675,2.862) 13(-3.675,-2.862) 24(3.675,-2.862)
  rect 0.4x1.585 smd: 2(2.925,2.862) 3(2.275,2.862) 4(1.625,2.862) 5(0.975,2.862) 6(0.325,2.862) 7(-0.325,2.862) 8(-0.975,2.862) 9(-1.625,2.862) 10(-2.275,2.862) 11(-2.925,2.862) 14(-2.925,-2.862) 15(-2.275,-2.862) 16(-1.625,-2.862) 17(-0.975,-2.862) 18(-0.325,-2.862) 19(0.325,-2.862) 20(0.975,-2.862) 21(1.625,-2.862) 22(2.275,-2.862) 23(2.925,-2.862)
FTP_65
  rect 0.45x0.55 smd: 1(-0.425,0) 2(0.425,0)
FTP_65#2
  rect 0.45x0.55 smd: 1(0.425,0) 2(-0.425,0)
FTP_67
  rect 0.72x0.8 smd: 1(0.64,0) 2(-0.64,0)
FTP_71
  round 1.8 hole 1.1: 1(0,0)
FTP_73
  round 2 hole 1: 1(-6.25,0) 2(6.25,0)
FTP_75
  round 2.2 hole 1.1: 1(-11.25,0) 2(11.25,0)
FTP_81
  rect 1.1x2 smd: A(-2.25,0) C(2.25,0)
FTP_85
  rect 1.212x1.2 smd: A(-1.494,0) C(1.494,0)
FTP_94
  round 2 hole 1: 1(-3.6,-4.3) 2(3.6,-4.3)
  round 1.8 hole 0.9: 3(2.575,2.7) 4(-2.575,2.7)
FTP_96
  round 3.2 hole 1.6: 1(-8.89,6.35) 2(-8.89,-6.35) 6(-3.81,6.35) 7(-3.81,-6.35)
  round 2.2 hole 1.1: 3(8.89,6.35) 4(8.89,0) 5(8.89,-6.35)
FTP_98
  round 2.4 hole 1.2: 1(0,0) 2(10,0)
FTP_106
  rect 1.405x3.4 smd: 1(-2.902,0) 2(2.902,0)
FTP_112
  rect 0.825x1.795 smd: 1(-2.042,-2.558) 4(2.042,-2.558) 5(2.042,2.558) 8(-2.042,2.558)
  rect 0.55x1.795 smd: 2(-0.635,-2.558) 3(0.635,-2.558) 6(0.635,2.558) 7(-0.635,2.558)
FTP_116
  round 3.8 hole 2.8: 1(0,0)
FTP_118
  round 3 hole 1.5: 1(0,-11) 2(0,11)
FTP_120
  round 2.2 hole 1.1: 1(-3.75,1.3) 2(3.75,-1.3)
FTP_128
  rect 0.6x1.46 smd: 1(-3.025,-2.925) 10(3.025,-2.925) 11(3.025,2.925) 20(-3.025,2.925)
  rect 0.4x1.46 smd: 2(-2.275,-2.925) 3(-1.625,-2.925) 4(-0.975,-2.925) 5(-0.325,-2.925) 6(0.325,-2.925) 7(0.975,-2.925) 8(1.625,-2.925) 9(2.275,-2.925) 12(2.275,2.925) 13(1.625,2.925) 14(0.975,2.925) 15(0.325,2.925) 16(-0.325,2.925) 17(-0.975,2.925) 18(-1.625,2.925) 19(-2.275,2.925)
I8K123
  rect 0.825x1.795 smd: 1(-4.583,-2.558) 8(4.583,-2.558) 9(4.583,2.558) 16(-4.583,2.558)
  rect 0.55x1.795 smd: 2(-3.175,-2.558) 3(-1.905,-2.558) 4(-0.635,-2.558) 5(0.635,-2.558) 6(1.905,-2.558) 7(3.175,-2.558) 10(3.175,2.558) 11(1.905,2.558) 12(0.635,2.558) 13(-0.635,2.558) 14(-1.905,2.558) 15(-3.175,2.558)
KC00050AKP
  rect 0.45x0.55 smd: 1(-0.425,0) 2(0.425,0)
KC00050AKP#2
  rect 0.45x0.55 smd: 1(0.425,0) 2(-0.425,0)
KC00060AKP
  rect 0.8x1.25 smd: 1(-0.9,0) 2(0.9,0)
KC00060AKP#2
  rect 0.8x1.25 smd: 1(0.9,0) 2(-0.9,0)
KC00140AKP01
  rect 1.15x1.8 smd: 1(1.375,0) 2(-1.375,0)
KC01670AKP
  rect 0.72x0.8 smd: 1(-0.64,0) 2(0.64,0)
KC01670AKP#2
  rect 0.72x0.8 smd: 1(0.64,0) 2(-0.64,0)
LITTELFUSE_0215_PHI5_5_V_A_2
  round 3 hole 2: 1(0,0) 2(10,0)
LOCAL_4PIN_SO6L_A
  rect 0.6x1.45 smd: 1(-1.27,-4.575) 3(1.27,-4.575) 4(1.27,4.575) 6(-1.27,4.575)
LOCAL_7460305_A
  round 2.2 hole 1.6: 1(-3.81,-3.81) 2(-1.27,-3.81) 3(1.27,-3.81) 4(3.81,-3.81) 5(3.81,3.81) 6(1.27,3.81) 7(-1.27,3.81) 8(-3.81,3.81)
LOCAL_AL_CAP_F30_A
  round 0.01 hole 0.8 unplated: (0,0)
  round 5.08 hole 2.6: 1(-5,0) 2(5,0)
LOCAL_BPUS15_25_A
  round 2.7 hole 1.8: 1(0,0)
LOCAL_CTW18A27UH
  oval 7.4x2.5 hole 6.4x1.5: F(7,-8) S(-7,8)
LOCAL_DE2E3SA222MN3AT02F
  round 1.4 hole 0.9: 1(0,0) 2(7.5,0)
LOCAL_G5PZ_1A
  round 1.5 hole 1: 1(0,0) 4(0,7.5)
  round 1.95 hole 1.3: 2(16.5,0) 3(20,7.5)
LOCAL_GSIB2580_A
  round 2.54 hole 1.6: 1(0,0) 2(10,0) 3(17.5,0) 4(25,0)
LOCAL_I8K0A8
  rect 0.825x1.795 smd: 1(4.582,4.72) 8(-4.582,4.72) 9(-4.582,-4.72) 16(4.582,-4.72)
  rect 0.55x1.795 smd: 2(3.175,4.72) 3(1.905,4.72) 4(0.635,4.72) 5(-0.635,4.72) 6(-1.905,4.72) 7(-3.175,4.72) 10(-3.175,-4.72) 11(-1.905,-4.72) 12(-0.635,-4.72) 13(0.635,-4.72) 14(1.905,-4.72) 15(3.175,-4.72)
LOCAL_LDFW013412YV_V0E_A
  round 3.15 hole 2.1: 1(-10,5) 2(10,5) 3(10,-5) 4(-10,-5)
LOCAL_LONGHOLE_250_450
  oval 6.5x4.5 hole 4.5x2.5: 1(0,0)
LOCAL_LONGHOLE_350_700
  oval 9x5.5 hole 7x3.5: 1(0,0)
LOCAL_RDER73A104K5B1H03B_A
  round 2.6 hole 1.3: 1(-0.02,0) 2(4.98,0)
LOCAL_SOIC_7_A
  rect 1.528x0.65 smd: 1(-2.711,1.905) 2(-2.711,0.635) 3(-2.711,-0.635) 4(-2.711,-1.905) 5(2.711,-1.905) 6(2.711,-0.635) 7(2.711,1.905)
LOCAL_SOPADVANCE_E_01_A
  custom 1.09x1.09 smd: (0,0)
  rect 0.55x1.05 smd: 1(-1.905,-2.975) 2(-0.635,-2.975) 3(0.635,-2.975) 4(1.905,-2.975) 5(1.905,2.975) 6(0.635,2.975) 7(-0.635,2.975) 8(-1.905,2.975)
LOCAL_TAM0545
  round 2.5 hole 1.4: 1(-13.5,-17.7) 3(-4.5,-17.7) 4(4.5,-17.7) 6(13.5,-17.7) 7(13.5,17.7) 8(9,17.7) 9(4.5,17.7) 10(-4.5,17.7) 11(-9,17.7) 12(-13.5,17.7)
LOCAL_TAM_PQ20_36_5
  round 1.575 hole 1.067: 1(-10.1,-10.15) 2(-6.3,-10.15) 3(-2.5,-10.15) 4(2.5,-10.15) 5(6.3,-10.15) 6(10.1,-10.15) 7(10.04,10.15) 8(7.54,10.15) 9(5.04,10.15) 10(2.54,10.15) 11(-2.54,10.15) 12(-5.04,10.15) 13(-7.54,10.15) 14(-10.04,10.15)
LOCAL_TH350_P550
  round 5.5 hole 3.5: 1(0,0)
LOCAL_TMSD_Y3001
  oval 5x3.2 hole 3.5x1.7: 1(0,-6) 2(0,6)
LOCAL_TO_220_2L_A
  round 1.778 hole 1.3: A(0,0) C(5.08,0)
LOCAL_TO_220SIS_02_A
  round 1.9 hole 1.3: D(0,-5) G(-2.5,-0.05) S(2.5,0)
LOCAL_Y5JA_330JPTL3_5_A
  round 1.778 hole 1.2: 1(-5,0) 2(5,0)
MM00340AKP
  rect 0.5x0.9 smd: D(0,0.65)
  rect 0.4x0.9 smd: G(-0.4,-0.65) S(0.4,-0.65)
MM00730AKP
  rect 0.4x0.95 smd: 1(-0.65,-0.975) 2(0,-0.975) 3(0.65,-0.975) 4(0.65,0.975) 5(-0.65,0.975)
MM00730AKP#2
  rect 0.4x0.95 smd: 1(0.65,0.975) 2(0,0.975) 3(-0.65,0.975) 4(-0.65,-0.975) 5(0.65,-0.975)
MM01320AKP
  rect 1x2.25 smd: 1(-2.3,-2.775) 2(0,-2.775) 3(2.3,-2.775)
  rect 3.2x2.25 smd: 4(0,2.775)
MMK01670AKP
  rect 1.212x1.2 smd: A(-1.494,0) C(1.494,0)
R8100A
  rect 1.405x3.4 smd: 1(-2.902,0) 2(2.902,0)
R8100A#2
  rect 1.405x3.4 smd: 1(2.902,0) 2(-2.902,0)
RDP10020ATP
  round 1.9 hole 1.65: D(5.44,0) G(0,0) S(10.88,0)
SIK00180ATP_RD244_A
  round 1.4 hole 0.9: 1(-5.25,0) 2(12.75,0)
SOT_23_6_KA
  rect 0.825x1.56 smd: 1(-1.087,-1.075) 3(1.087,-1.075) 4(1.087,1.075) 6(-1.087,1.075)
  rect 0.55x1.56 smd: 2(0,-1.075) 5(0,1.075)
unnamed#2
  round 0.01 hole 3.2 unplated: (0,0)
US2H_A
  custom 0.2x0.2 smd: A(1.25,0)
  rect 2x1.1 smd: C(-0.65,0)

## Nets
P48V: C510.2 C511.2 C512.2 CN501.1 CN501.2 CN501.3 CN501.4 CN501.5 CN501.6 CN501.7 CN501.8 CN503.1 IC501.4 Q501.5 Q501.6 Q501.7 Q501.8 Q502.5 Q502.6 Q502.7 Q502.8 Q503.5 Q503.6 Q503.7 Q503.8 Q504.5 Q504.6 Q504.7 Q504.8
VCC5R0_1: C104.2 C105.2 C115.2 C116.2 C309.2 C413.2 IC101.3 IC101.8 IC102.3 IC102.8 IC304.16 IC403.5
VCC5R0_2: C351.2 IC304.1 R454.2
VCC12R0_1: C11.2 D1.C DP403.1 IC51.1 IC51.8 R4.1 R51.1 R59.2 R67.2 R85.1 R106.1 R117.1 R314.2 R316.2 R318.2 R320.2 R322.2 R416.1 R417.1 RY1.4
VCC12R0_2: CN504.1 CN504.2 DP451.1 IC303.6 R151.1 R201.1 R260.1 R452.2 R453.1
ACIN: C301.2 D51.C D52.C R301.1
CONN002: C119.1 C120.1 CN101.1 CN104.1 D113.A IC102.14 Q103.S Q104.D R121.1
CONN003: CN103.1 CN106.1 D108.A D109.C L101.2
CONN004: C501.2 C502.2 C503.2 C504.2 C505.2 C506.2 C507.2 C508.2 C509.2 DP503.1 IC501.3 IC501.6 L151.F L201.F Q501.1 Q501.2 Q501.3 Q502.1 Q502.2 Q502.3 Q503.1 Q503.2 Q503.3 Q504.1 Q504.2 Q504.3 R162.2 R163.2 R212.2 R213.2 R287.2 R501.2 R502.2 R503.2
CS: D251.C R282.2 R284.2
CSA: D58.C D62.C DP52.1 R52.2 R59.1 R68.1
CSB: D63.C D67.C DP54.1 R60.2 R67.1 R69.1
FG1: C2.1 C3.1 C4.1 C5.1 C7.1 C8.1 CN1.2
FG2: C512.1 C513.2 R505.1 R506.1
HS1_1: R422.2
HS1_2: R423.2
LGND: C151.1 C152.1 C153.1 C156.1 C157.1 C158.1 C159.1 C201.1 C202.1 C203.1 C206.1 C207.1 C208.1 C209.1 C251.1 C252.1 C253.1 C254.1 C255.1 C351.1 C414.2 C451.1 C452.1 C453.1 C501.1 C502.1 C503.1 C504.1 C505.1 C506.1 C507.1 C508.1 C510.1 C511.1 C513.1 CN502.1 CN502.2 CN502.3 CN502.4 CN502.5 CN502.6 CN502.7 CN502.8 CN503.2 CN504.3 CN504.4 D153.C D203.C DP153.1 DP156.1 DP257.1 DP501.1 IC151.3 IC201.3 IC251.24 IC304.2 IC304.8 IC451.2 IC501.2 Q151.1 Q151.2 Q151.3 Q152.1 Q152.2 Q152.3 Q153.1 Q153.2 Q153.3 Q154.1 Q154.2 Q154.3 Q201.1 Q201.2 Q201.3 Q202.1 Q202.2 Q202.3 Q203.1 Q203.2 Q203.3 Q204.1 Q204.2 Q204.3 Q351.S R154.1 R155.1 R158.1 R159.1 R160.1 R161.1 R204.1 R205.1 R208.1 R209.1 R210.1 R211.1 R251.1 R252.1 R253.1 R254.1 R255.1 R256.1 R257.1 R258.1 R259.1 R262.1 R264.1 R267.1 R269.1 R271.1 R273.1 R275.1 R276.1 R281.1 R283.1 R284.1 R285.1 R291.1 R352.1 R356.1 R359.1 R362.1 R365.1 R451.1 R501.1 R502.1 R503.1 R505.2 R506.2 T101.3 T401.8 T401.9
OUTA1: IC304.14 R104.2
OUTA2: DP251.1 IC251.22 R355.2
OUTB1: IC304.13 R103.2
OUTB2: DP252.1 IC251.21 R358.2
OUTC1: IC304.12 R115.2
OUTC2: DP253.1 IC251.20 R361.2
OUTD1: IC304.11 R114.2
OUTD2: DP254.1 IC251.19 R364.2
OUTE: DP255.1 IC251.18 R164.1 R214.1
OUTF: DP256.1 IC251.17 R165.1 R215.1
PFC_OFF: C66.2 DP61.1 IC52.18 R308.1
PFC_OUT: C51.2 C52.2 C78.2 C79.2 D55.1 D56.C D57.C DP51.1 F401.1 R92.2 R101.2 R309.1 T101.2
PN: C11.1 C51.1 C52.1 C53.1 C54.1 C55.1 C56.1 C57.1 C58.1 C59.1 C60.1 C61.1 C62.1 C63.1 C64.1 C65.1 C66.1 C67.1 C68.1 C69.1 C70.1 C71.1 C73.1 C75.1 C77.1 C78.1 C79.1 C81.1 C82.1 C101.1 C102.1 C103.1 C104.1 C105.1 C106.1 C107.1 C110.1 C111.1 C112.1 C113.1 C114.1 C115.1 C116.1 C117.1 C118.1 C121.1 C301.1 C302.1 C303.1 C304.1 C305.1 C306.1 C307.1 C308.1 C309.1 C310.1 C311.1 C401.1 C405.1 C407.1 C408.1 C409.1 C410.1 C411.1 C412.1 C413.1 C414.1 D55.4 D68.A D107.A D109.A D116.A D302.A DP1.1 DP59.1 DP304.1 HS1.1 HS2.1 IC51.3 IC52.16 IC101.4 IC101.5 IC101.9 IC102.4 IC102.5 IC102.9 IC301.2 IC302.2 IC304.9 IC304.15 IC401.4 IC403.2 Q1.S Q51.S Q52.S Q102.S Q104.S Q301.S Q302.S Q303.S R5.1 R6.1 R52.1 R56.1 R60.1 R64.1 R74.1 R76.1 R78.1 R79.1 R80.1 R82.1 R84.1 R88.1 R89.1 R90.1 R91.1 R96.1 R102.1 R105.2 R113.1 R116.2 R124.1 R306.1 R312.1 R315.1 R317.1 R319.1 R321.1 R323.1 R404.1 R405.1 R406.1 R411.1 R412.1 R414.1 R418.1 R419.1 R420.1 R421.1 R422.1 R423.1 T51.2 T52.2 T401.4
RY_OFF: C311.2 D303.C D304.C IC301.4 Q302.G R4.2 R7.1
SIG1: C1.2 C2.2 F1.2 L1.1 R1.2 RV1.1
SIG2: C1.1 C3.2 CN1.3 CN2.3 L1.4 R2.1 RV1.2
SIG6: C8.2 C9.1 D52.A D54.A D55.3 L2.3 L52.1
SIG8: C9.2 D51.A D53.A D55.2 L51.1 R3.2 RY1.2
SIG9: IC1.2 IC1.3 R1.1
SIG10: IC1.6 IC1.7 R2.2
SIG11: D57.A L52.2 T52.4
SIG0012: C7.2 L2.2 R3.1 RY1.3
SIG12: D56.A L51.2 T51.4
SIG0013: D1.A Q1.D R6.2 RY1.1
SIG0014: Q1.G R5.2 R7.2
SIG15: D63.A R61.2 T52.1
SIG16: C60.2 R61.1
SIG18: Q52.D T52.3
SIG20: D58.A R53.2 T51.1
SIG21: C58.2 R53.1
SIG0022: C54.2 IC51.2 R97.2
SIG22: Q51.D T51.3
SIG0023: C53.2 IC51.4 R98.2
SIG23: L54.1 R62.2 R63.2
SIG24: C61.2 D67.A R65.2 R66.2
SIG0024: C76.1 R91.2
SIG25: C59.2 D62.A R57.2 R58.2
SIG0025: C74.1 R90.2
SIG0026: C70.2 IC52.13 R86.2 R87.2
SIG27: L53.1 R54.2 R55.2
SIG0027: C67.2 C68.2 D68.C IC52.15 R85.2
SIG0028: R83.1 R84.2
SIG0029: IC52.19 R83.2
SIG30: D59.A D60.C D61.C IC51.7 R57.1
SIG0057: IC251.2 R272.1 R273.2
SIG0058: C256.1 R286.1
SIG0059: C257.1 C258.1 IC251.3 R286.2 R289.1 R290.2
SIG100: D64.C R63.1
SIG101: D65.A R62.1
SIG102: D64.A D65.C D66.C IC51.5 R65.1
SIG104: C55.2 C56.2 C57.2 IC51.6 R51.2
SIG105: D60.A R54.1
SIG106: D59.C R55.1
SIG115: C204.2 CN201.1 D207.A Q201.5 Q201.6 Q201.7 Q201.8 Q202.5 Q202.6 Q202.7 Q202.8
SIG122: C509.1 IC501.1
SIG136: IC501.5 R504.1
SIG141: DP502.1 Q501.4 Q502.4 Q503.4 Q504.4 R504.2
SIG193: CN1.1 CN2.1 F1.1
SIG199: C4.2 C6.2 L1.2 L2.1
SIG200: C5.2 C6.1 L1.3 L2.4
SIG00210: R93.1 R94.2
SIG00211: C64.2 DP56.1 IC52.5 R72.1 R73.2
SIG00212: R95.1 R96.2
SIG00213: IC52.7 R81.2
SIG00214: C77.2 DP60.1 IC52.4 R94.1 R95.2
SIG00215: R81.1 R82.2
SIG00216: R77.1 R78.2
SIG00217: R73.1 R74.2
SIG00218: R70.1 R71.2
SIG00219: C69.2 IC52.10 R86.1 R87.1 R88.2
SIG00220: C73.2 C74.2 IC52.12
SIG00221: C71.2 C72.2 IC52.11
SIG00222: R71.1 R72.2
SIG00223: IC52.6 R79.2 R80.2
SIG00224: IC52.20 R77.2
SIG00225: C63.2 IC52.8 R69.2
SIG00226: C65.2 IC52.1
SIG00227: R92.1 R93.2
SIG00228: IC52.2 R76.2
SIG00229: C75.2 C76.2 IC52.3
SIG00230: C72.1 R89.2
SIG00231: C62.2 IC52.9 R68.2
SIG00232: D53.C D54.C R70.2
SIG00233: DP57.1 IC52.17 R98.1
SIG00234: DP58.1 IC52.14 R97.1
SIG00331: R101.1 R102.2
SIG00332: D251.A R251.2 T101.5
SIG00333: D105.A D106.C D107.C IC101.10
SIG00334: C108.2 D101.C IC101.16
SIG00335: D101.A R107.1
SIG00336: C106.2 C107.2 IC101.11 R106.2 R107.2
SIG00337: D105.C R111.1
SIG00338: D106.A R112.1
SIG00339: D102.A D103.C D104.C IC101.15
SIG00340: D103.A R109.1
SIG00341: D102.C R108.1
SIG00342: C110.2 Q102.G R111.2 R112.2 R113.2
SIG00343: C111.2 D108.C Q101.D Q103.D T101.1
SIG00344: D111.C R119.1
SIG00345: C119.2 D110.C IC102.16
SIG00346: D114.A D115.C D116.C IC102.10
SIG00347: D111.A D112.C D113.C IC102.15
SIG00348: C114.2 IC102.6 R116.1
SIG00349: D114.C R122.1
SIG00350: D115.A R123.1
SIG00351: C120.2 Q103.G R119.2 R120.2 R121.2
SIG00352: C121.2 Q104.G R122.2 R123.2 R124.2
SIG00353: C117.2 C118.2 IC102.11 R117.2 R118.2
SIG00354: D110.A R118.1
SIG00355: D112.A R120.1
SIG00356: C109.2 Q101.G R108.2 R109.2 R110.2
SIG00357: C103.2 IC101.6 R105.1
SIG00358: C102.2 DP101.1 IC101.1 R104.1
SIG00359: C101.2 DP102.1 IC101.2 R103.1
SIG00360: C113.2 DP103.1 IC102.1 R115.1
SIG00361: C112.2 DP104.1 IC102.2 R114.1
SIG00362: C108.1 C109.1 D104.A IC101.14 L101.1 Q101.S Q102.D R110.1
SIG00429: C151.2 C152.2 C153.2 IC151.6 R151.2
SIG00430: D151.C R152.1
SIG00431: D152.A R153.1
SIG00432: D154.C R156.1
SIG00433: D156.A R157.1
SIG00434: D201.C R202.1
SIG00435: D202.A R203.1
SIG00436: D204.C R206.1
SIG00437: D206.A R207.1
SIG00438: D201.A D202.C D203.A IC201.7
SIG00439: DP155.1 Q153.4 Q154.4 R156.2 R157.2 R158.2
SIG00440: DP202.1 Q203.4 Q204.4 R206.2 R207.2 R208.2
SIG00441: C154.1 R155.2
SIG00442: C155.1 R159.2
SIG00443: C205.1 R209.2
SIG00444: C204.1 R205.2
SIG00445: C205.2 CN202.1 D208.A Q203.5 Q203.6 Q203.7 Q203.8 Q204.5 Q204.6 Q204.7 Q204.8
SIG00446: CN153.1 DP157.1 L151.S
SIG00447: C154.2 CN151.1 D157.A DP151.1 Q151.5 Q151.6 Q151.7 Q151.8 Q152.5 Q152.6 Q152.7 Q152.8
SIG00448: CN203.1 DP203.1 L201.S
SIG00449: DP152.1 Q151.4 Q152.4 R152.2 R153.2 R154.2
SIG00450: DP201.1 Q201.4 Q202.4 R202.2 R203.2 R204.2
SIG00451: C158.2 IC151.2 R164.2
SIG00452: C159.2 IC151.4 R165.2
SIG00453: C208.2 IC201.2 R214.2
SIG00454: D153.NC D154.A D156.C IC151.5
SIG00455: D203.NC D204.A D206.C IC201.5
SIG00456: D151.A D152.C D153.A IC151.7
SIG00457: C155.2 CN152.1 D158.A DP154.1 Q153.5 Q153.6 Q153.7 Q153.8 Q154.5 Q154.6 Q154.7 Q154.8
SIG00458: C156.2 C157.2 D157.C D158.C R160.2 R161.2 R162.1 R163.1
SIG00459: C201.2 C202.2 C203.2 IC201.6 R201.2
SIG00460: C209.2 IC201.4 R215.2
SIG00461: C206.2 C207.2 D207.C D208.C R210.2 R211.2 R212.1 R213.1
SIG00510: R277.2 R278.2 R282.1
SIG00511: R278.1 R279.1 R280.2
SIG00512: C252.2 C253.2 IC251.23 R260.2
SIG00513: IC251.6 R253.2 R254.2
SIG00514: IC251.7 R255.2 R256.2
SIG00515: IC251.9 R259.2
SIG00516: IC251.8 R257.2 R258.2
SIG00517: IC251.12 R280.1 R281.2 R283.2
SIG00518: IC251.10 R263.1 R264.2 R265.1
SIG00519: C256.2 C257.2 IC251.4 R285.2
SIG00520: R287.1 R288.2 R292.2
SIG00521: R288.1 R289.2
SIG00522: C258.2 R292.1
SIG00523: R290.1 R291.2
SIG00524: R261.1 R262.2
SIG00525: IC251.11 R261.2
SIG00526: C255.2 DP258.1 IC251.15 R266.2 R274.2 R276.2 R277.1
SIG00527: IC251.13 R266.1 R267.2 R268.1 R269.2
SIG00528: IC251.14 R270.1 R271.2 R274.1 R275.2
SIG00772: R363.1 R364.1 R365.2
SIG00774: IC304.6 R363.2
SIG00777: IC304.3 R354.2
SIG00781: R360.1 R361.1 R362.2
SIG00783: IC304.4 R357.2
SIG00789: R357.1 R358.1 R359.2
SIG00791: IC304.5 R360.2
SIG00794: R354.1 R355.1 R356.2
SIG00797: C310.2 D306.C DP302.1 IC302.5 R312.2 R313.1
SIG00799: IC303.4 R351.2
SIG00817: DP404.1 R418.2
SIG00818: DP405.1 R419.2
SIG00819: DP406.1 R420.2
SIG00820: DP407.1 R421.2
SIG00823: C453.2 IC451.5 R454.1
SIG00826: C452.2 IC451.1 IC451.3 R453.2
SIG00837: D451.1 D451.3 T401.12 T401.13
SIG00839: C411.2 D404.A D405.C IC402.2 IC402.4 R415.2 R416.2
SIG00841: D401.A Q401.D T401.3
SIG00842: C402.1 C403.1 D401.C R401.1
SIG00843: D402.A R409.2 R413.2 T401.6
SIG00847: Q401.S R403.1 R404.2 R405.2 R406.2 R407.2
SIG00848: C407.2 R413.1
SIG00849: IC401.2 R409.1 R410.2
SIG00851: DP402.1 IC401.5 R407.1
SIG00852: C451.2 D451.2 R451.2 R452.1
SIG00853: C401.2 C402.2 C403.2 F401.2 IC401.7 R401.2 T401.1
SIG00854: IC401.3 R412.2
SIG00855: D402.C R408.2
SIG00856: C405.2 DP401.1 IC401.1 R408.1
SIG00858: C412.2 IC403.1 IC403.3 R417.2
SIG00859: D403.A T401.5
SIG00860: C408.2 C409.2 D403.C D404.C IC402.3
SIG00861: R410.1 R411.2
SIG00862: C410.2 D405.A IC402.1 R414.2 R415.1
SIG00863: IC401.6 R402.1
SIG00864: Q401.G R402.2 R403.2
SIG007100: C304.2 C305.2 IC301.1
SIG007101: IC303.3 R317.2
SIG007102: D304.A R308.2
SIG007103: IC303.1 Q301.D R316.1
SIG007104: C303.2 IC301.3
SIG007105: Q351.G R351.1 R352.2
SIG007106: D303.A R307.2
SIG007109: R305.1 R306.2
SIG007110: R310.2 R311.1
SIG007111: R303.2 R304.1
SIG007112: C306.2 DP303.1 IC302.3 Q303.D
SIG007115: R311.2 R313.2
SIG007116: C307.2 C308.2 IC302.1
SIG007118: Q351.D R353.1
SIG007120: R309.2 R310.1
